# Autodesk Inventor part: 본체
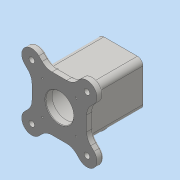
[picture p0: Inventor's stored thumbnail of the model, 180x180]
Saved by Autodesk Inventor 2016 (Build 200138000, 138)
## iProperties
Created: 2019-11
Part Number: 본체
Material: 일반
Document SubType Name: Modeling
Designer: user
Density: 1 g/cm^3
Appearance: 기본값
Author: user
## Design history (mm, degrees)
sketch "스케치2"
  geometry: L1 (-49, 49)-(49, 49); L2 (49, 49)-(49, -49); L3 (49, -49)-(-49, -49); L4 (-49, -49)-(-49, 49); L5 (-49, 49)-(49, -49); L6 (49, 49)-(-49, -49); L7 (49.497, 49.497)-(-49.497, -49.497); L8 (36.77, 62.225)-(-62.225, -36.77); L9 (-36.77, -62.225)-(62.225, 36.77); L10 (49.497, -49.497)-(-49.497, 49.497); L11 (62.225, -36.77)-(-36.77, 62.225); L12 (-62.225, 36.77)-(36.77, -62.225); A1 r 18 centre (49.497, 49.497) between (62.225, 36.77) and (36.77, 62.225); A2 r 18 centre (-49.497, -49.497) between (-62.225, -36.77) and (-36.77, -62.225); A3 r 18 centre (49.497, -49.497) between (36.77, -62.225) and (62.225, -36.77); A4 r 18 centre (-49.497, 49.497) between (-36.77, 62.225) and (-62.225, 36.77); 1 further point
  constraints: 28 end point, 8 point on circle, 8 tangent, 4 centre point, 4 midpoint, 4 parallel, 2 perpendicular, 1 horizontal, 1 point on line
  dimensions: "d7" = 98 distance of L2.end L3.end; "d8" = 98 distance of L1.end L2.end; "d9" = 18 radius of A3; "d10" = 18 radius of A1; "d11" = 70 distance of point (0, 0) L7.start; "d12" = 70 distance of point (0, 0) L10.start
extrude "돌출1" new body sketch "스케치2" distance "d13" = 12; taper "d14" = 0 deg
sketch "스케치3"
  geometry: L1 (-40, 40)-(40, 40); L2 (40, 40)-(40, -40); L3 (40, -40)-(-40, -40); L4 (-40, -40)-(-40, 40); L5 (-40, 40)-(40, -40); L6 (40, 40)-(-40, -40); 1 further point
  constraints: 12 end point, 2 midpoint, 2 parallel, 1 horizontal, 1 perpendicular
  dimensions: "d19" = 80 distance of L1.start L1.end; "d20" = 80 distance of L1.end L2.end
extrude "돌출2" join sketch "스케치3" distance "d21" = 98; taper "d22" = 0 deg
sketch "스케치4"
  geometry: C1 r 25 at (0, 0); 1 further point
  constraints: 1 centre point, 1 coincident
  dimensions: "d23" = 50 diameter of C1
extrude "돌출3" cut sketch "스케치4" distance "d24" = 12; taper "d25" = 0 deg
node "작업 평면1"
sketch "스케치5"
  geometry: C1 r 35 at (0, 0); 1 further point
  constraints: 1 centre point, 1 coincident
  dimensions: "d27" = 70 diameter of C1
extrude "돌출4" cut sketch "스케치5" distance "d28" = 86; taper "d29" = 0 deg
chamfer "모따기1" distance "d30" = 1; stored, may be unused: second distance "d31" = 2, angle "d32" = 45 deg
chamfer "모따기2" distance "d33" = 1; stored, may be unused: second distance "d34" = 2, angle "d35" = 45 deg
sketch "스케치6"
  geometry: L1 (-30, 30)-(30, 30); L2 (30, 30)-(30, -30); L3 (30, -30)-(-30, -30); L4 (-30, -30)-(-30, 30); L5 (-30, 30)-(30, -30); L6 (30, 30)-(-30, -30); 2 further points
  constraints: 12 end point, 2 midpoint, 2 parallel, 1 coincident, 1 horizontal, 1 perpendicular
  dimensions: "d36" = 60 distance of L1.start L1.end; "d37" = 60 distance of L1.end L2.end
hole "구멍1" sketch "스케치6" at (-30, 30) diameter "d38" = 3.242; stored, may be unused: countersink angle "d42" = 90 deg, drill point angle "d44" = 118 deg; dims "d39" = 8, "d40" = 4, "d41" = 2, "d43" = 10
node "작업 평면2"
sketch "스케치8"
  geometry: L1 (-36.77, 12)-(-67.497, 12) reference; C1 r 20 at (0, 61); 2 further points
  constraints: 1 centre point, 1 vertical alignment
  dimensions: "d53" = 40 diameter of C1; "d54" = 49 distance from line of L1 C1.centre
extrude "돌출5" join sketch "스케치8" stored distance "d55" = 86; taper "d56" = 0 deg
sketch "스케치9"
  geometry: L1 (-66.636, -49)-(-29.544, -49) reference; L2 (-29.544, -49)-(-29.544, -61) reference; L3 (-29.544, -61)-(-66.636, -61) reference; L4 (-66.636, -61)-(-66.636, -49) reference; L5 (29.544, -49)-(66.636, -49) reference; L6 (66.636, -49)-(66.636, -61) reference; L7 (66.636, -61)-(29.544, -61) reference; L8 (29.544, -61)-(29.544, -49) reference; C1 r 20 at (0, 0) reference; 2 further points
  constraints: 1 coincident
hole "구멍2" sketch "스케치9" at (0, 0) diameter "d57" = 25; stored, may be unused: countersink angle "d61" = 90 deg, drill point angle "d63" = 0 deg; dims "d58" = 8, "d59" = 30, "d60" = 8, "d62" = 40
sketch "스케치10"
  geometry: L1 (40, -40)-(-40, -40) reference; L2 (-40, -40)-(-40, 40) reference; L3 (-40, 40)-(40, 40) reference; L4 (40, 40)-(40, -40) reference; L5 (49, 23.544)-(49, -23.544) reference; L6 (49, -23.544)-(62.225, -36.77) reference; L7 (36.77, -62.225)-(23.544, -49) reference; L8 (23.544, -49)-(-23.544, -49) reference; L9 (-23.544, -49)-(-36.77, -62.225) reference; L10 (-62.225, -36.77)-(-49, -23.544) reference; L11 (-49, -23.544)-(-49, 23.544) reference; L12 (-49, 23.544)-(-62.225, 36.77) reference; L13 (-36.77, 62.225)-(-23.544, 49) reference; L14 (-23.544, 49)-(23.544, 49) reference; L15 (23.544, 49)-(36.77, 62.225) reference; L16 (62.225, 36.77)-(49, 23.544) reference; C1 r 35 at (0, 0) reference; C2 r 25 at (0, 0) reference; A1 r 18 centre (49.497, -49.497) between (36.77, -62.225) and (62.225, -36.77) reference; A2 r 18 centre (-49.497, -49.497) between (-62.225, -36.77) and (-36.77, -62.225) reference; A3 r 18 centre (-49.497, 49.497) between (-36.77, 62.225) and (-62.225, 36.77) reference; A4 r 18 centre (49.497, 49.497) between (62.225, 36.77) and (36.77, 62.225) reference; 2 further points
  constraints: 1 coincident
hole "구멍3" sketch "스케치10" at (-49.497, 49.497) diameter "d64" = 10; stored, may be unused: countersink angle "d68" = 90 deg, drill point angle "d70" = 0 deg; dims "d65" = 8, "d66" = 18, "d67" = 4, "d69" = 40
fillet "모깎기1" dims "d74" = 25
chamfer "모따기3" distance "d75" = 1; stored, may be unused: second distance "d76" = 2, angle "d77" = 45 deg
sketch "스케치11"
  geometry: L1 (80, 98)-(0, 98) reference; 2 further points
  constraints: 1 vertical alignment, 1 other
  dimensions: "d78" = 10 distance from line of L1 point (40, 88)
feature "엠보싱1" sketch "스케치11" dims "d7" = 98, "d8" = 98, "d9" = 18, "d10" = 18, "d11" = 70, "d12" = 70, "d79" = 0.5, "d80" = 0
fillet "모깎기2" dims "d81" = 3
fillet "모깎기3" dims "d82" = 3
fillet "모깎기4" dims "d83" = 10
fillet "모깎기5" dims "d84" = 3
node "솔리드1"
mirror "대칭1"
pattern_linear "직사각형 패턴1" dims "d47" = 60
mirror "대칭2"
pattern_circular "원형 패턴1" dims angle "d72" = 360 deg
node "절단 모서리 투영1"
node "절단 모서리 투영2"
other parameters: "d26" = -55, "d52" = -55
